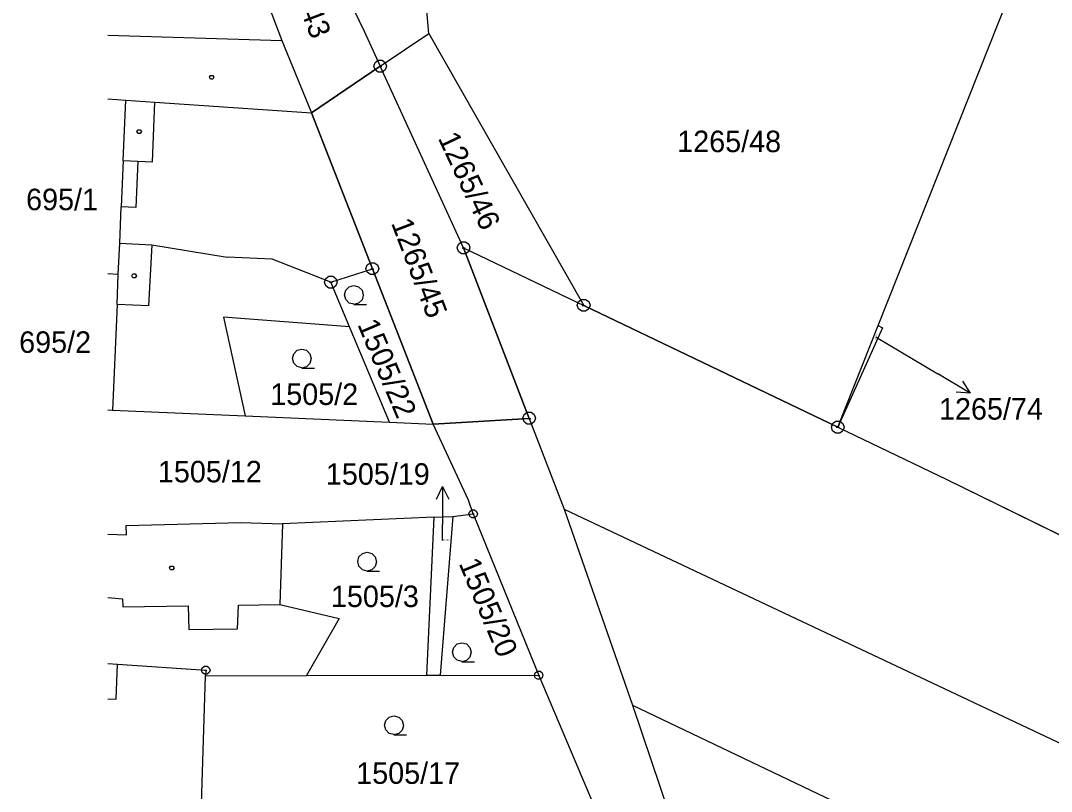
# Model space of a CAD drawing. Extents: x -777309 to -774195, y -1144706 to -1143600.
# Drawn here: x -777306.9 to -777225.3, y -1143975 to -1143914.1 of the extents above; entities that cross this region are included whole.
import ezdxf

# ---------------------------------------------------------------- set-up
doc = ezdxf.new("R2010")
doc.units = 0
for name, color, linetype in [('1', 7, 'Continuous'), ('11', 7, 'Continuous'), ('12', 7, 'Continuous'), ('2', 7, 'Continuous'), ('3', 7, 'Continuous'), ('4', 7, 'Continuous'), ('5', 7, 'Continuous'), ('7', 7, 'Continuous'), ('8', 7, 'Continuous')]:
    doc.layers.add(name, color=color, linetype=linetype)

msp = doc.modelspace()

# ---------------------------------------------------------------- linework, layer by layer
at = {"layer": '1'}
for p, q in [((-777286.27, -1143901.3), (-777279.72, -1143914.89)), ((-777239.05, -1143938.18), (-777226.25, -1143905.92)), ((-777288.2, -1143910.44), (-777286.22, -1143915.64)), ((-777274.6, -1143915.07), (-777274.79, -1143912.96)), ((-777279.72, -1143914.89), (-777278.44, -1143917.67)), ((-777286.22, -1143915.64), (-777283.88, -1143921.35)), ((-777278.44, -1143917.67), (-777274.6, -1143915.07)), ((-777283.88, -1143921.35), (-777278.44, -1143917.67)), ((-777271.84, -1143932.03), (-777278.44, -1143917.67)), ((-777300, -1143920.249), (-777298.57, -1143920.35)), ((-777298.57, -1143920.35), (-777296.28, -1143920.51)), ((-777296.28, -1143920.51), (-777283.88, -1143921.35)), ((-777279.06, -1143933.68), (-777283.88, -1143921.35)), ((-777299.16, -1143934.11), (-777299.05, -1143931.67)), ((-777299.05, -1143931.67), (-777296.52, -1143931.78)), ((-777296.52, -1143931.78), (-777290.55, -1143932.77)), ((-777287, -1143932.91), (-777290.55, -1143932.77)), ((-777271.84, -1143932.03), (-777266.65, -1143945.51)), ((-777271.84, -1143932.03), (-777262.34, -1143936.58)), ((-777282.34, -1143934.75), (-777287, -1143932.91)), ((-777300, -1143934.058), (-777299.16, -1143934.11)), ((-777282.34, -1143934.75), (-777279.06, -1143933.68)), ((-777277.16, -1143938.54), (-777279.06, -1143933.68)), ((-777280.87, -1143938.26), (-777282.34, -1143934.75)), ((-777242.24, -1143946.21), (-777262.34, -1143936.58)), ((-777280.87, -1143938.26), (-777290.83, -1143937.5)), ((-777290.83, -1143937.5), (-777289.12, -1143945.32)), ((-777277.71, -1143945.82), (-777280.87, -1143938.26)), ((-777274.26, -1143945.97), (-777277.16, -1143938.54)), ((-777242.24, -1143946.21), (-777239.05, -1143938.18)), ((-777238.7, -1143938.36), (-777242.24, -1143946.21)), ((-777239.05, -1143938.18), (-777238.7, -1143938.36)), ((-777300, -1143944.843), (-777299.61, -1143944.86)), ((-777299.61, -1143944.86), (-777289.12, -1143945.32)), ((-777289.12, -1143945.32), (-777277.71, -1143945.82)), ((-777277.71, -1143945.82), (-777274.26, -1143945.97)), ((-777266.65, -1143945.51), (-777274.26, -1143945.97)), ((-777266.65, -1143945.51), (-777263.88, -1143952.69)), ((-777271.45, -1143951.98), (-777274.26, -1143945.97)), ((-777242.24, -1143946.21), (-777233.61, -1143950.34)), ((-777233.61, -1143950.34), (-777182.11, -1143975.59)), ((-777271.08, -1143953.07), (-777271.45, -1143951.98)), ((-777272.69, -1143953.26), (-777271.08, -1143953.07)), ((-777271.08, -1143953.07), (-777265.9, -1143965.83)), ((-777263.88, -1143952.69), (-777214.44, -1143976.01)), ((-777263.88, -1143952.69), (-777258.48, -1143968.19)), ((-777298.53, -1143953.99), (-777289.46, -1143953.75)), ((-777298.52, -1143954.72), (-777298.53, -1143953.99)), ((-777289.46, -1143953.75), (-777286.17, -1143953.86)), ((-777286.17, -1143953.86), (-777286.39, -1143960.23)), ((-777274.18, -1143953.33), (-777286.17, -1143953.86)), ((-777274.76, -1143965.81), (-777274.18, -1143953.33)), ((-777274.18, -1143953.33), (-777272.69, -1143953.26)), ((-777272.69, -1143953.26), (-777273.69, -1143965.81)), ((-777300, -1143954.654), (-777298.52, -1143954.72)), ((-777286.39, -1143960.23), (-777281.7, -1143961.34)), ((-777281.7, -1143961.34), (-777284.26, -1143965.84)), ((-777300, -1143964.887), (-777299.23, -1143964.94)), ((-777299.23, -1143964.94), (-777292.24, -1143965.43)), ((-777292.24, -1143965.43), (-777292.26, -1143965.88)), ((-777292.6, -1143976.92), (-777292.26, -1143965.88)), ((-777292.26, -1143965.88), (-777284.26, -1143965.84)), ((-777284.26, -1143965.84), (-777274.76, -1143965.81)), ((-777274.76, -1143965.81), (-777273.69, -1143965.81)), ((-777273.69, -1143965.81), (-777265.9, -1143965.83)), ((-777265.9, -1143965.83), (-777261.12, -1143977.11)), ((-777258.48, -1143968.19), (-777252.93, -1143984.66)), ((-777258.48, -1143968.19), (-777214.18, -1143989.29))]:
    msp.add_line(p, q, dxfattribs=at)
msp.add_lwpolyline([(-777274.6, -1143915.07), (-777269.54, -1143923.97), (-777262.34, -1143936.58)], dxfattribs=at)
at = {"layer": '11'}
msp.add_lwpolyline([(-777286.27, -1143901.3), (-777279.72, -1143914.89), (-777278.44, -1143917.67), (-777283.88, -1143921.35), (-777279.06, -1143933.68), (-777277.16, -1143938.54), (-777274.26, -1143945.97), (-777266.65, -1143945.51), (-777271.84, -1143932.03), (-777262.34, -1143936.58), (-777242.24, -1143946.21), (-777233.61, -1143950.34), (-777182.11, -1143975.59)], dxfattribs=at)
at = {"layer": '12'}
for p, q in [((-777300, -1143920.249), (-777298.57, -1143920.35)), ((-777298.77, -1143925.12), (-777298.57, -1143920.35)), ((-777298.77, -1143925.12), (-777298.93, -1143928.78)), ((-777299.05, -1143931.67), (-777298.93, -1143928.78)), ((-777299.16, -1143934.11), (-777299.05, -1143931.67)), ((-777300, -1143934.058), (-777299.16, -1143934.11)), ((-777300, -1143934.058), (-777299.16, -1143934.11)), ((-777299.26, -1143936.5), (-777299.16, -1143934.11)), ((-777299.26, -1143936.5), (-777299.61, -1143944.86)), ((-777300, -1143944.843), (-777299.61, -1143944.86))]:
    msp.add_line(p, q, dxfattribs=at)
at = {"layer": '3'}
for points in [[(-777280.51, -1143936.49), (-777280.89, -1143936.39), (-777281.16, -1143936.12), (-777281.26, -1143935.75), (-777281.16, -1143935.38), (-777280.89, -1143935.11), (-777280.52, -1143935.01), (-777280.15, -1143935.11), (-777279.88, -1143935.38), (-777279.78, -1143935.76), (-777279.88, -1143936.14), (-777280.15, -1143936.41), (-777280.53, -1143936.51), (-777279.53, -1143936.51)], [(-777284.63, -1143941.51), (-777285.01, -1143941.41), (-777285.28, -1143941.14), (-777285.38, -1143940.77), (-777285.28, -1143940.4), (-777285.01, -1143940.13), (-777284.64, -1143940.03), (-777284.27, -1143940.13), (-777284, -1143940.4), (-777283.9, -1143940.78), (-777284, -1143941.16), (-777284.27, -1143941.43), (-777284.65, -1143941.53), (-777283.65, -1143941.53)], [(-777279.47, -1143957.58), (-777279.85, -1143957.48), (-777280.12, -1143957.21), (-777280.22, -1143956.84), (-777280.12, -1143956.47), (-777279.85, -1143956.2), (-777279.48, -1143956.1), (-777279.11, -1143956.2), (-777278.84, -1143956.47), (-777278.74, -1143956.85), (-777278.84, -1143957.23), (-777279.11, -1143957.5), (-777279.49, -1143957.6), (-777278.49, -1143957.6)], [(-777271.97, -1143964.73), (-777272.35, -1143964.63), (-777272.62, -1143964.36), (-777272.72, -1143963.99), (-777272.62, -1143963.62), (-777272.35, -1143963.35), (-777271.98, -1143963.25), (-777271.61, -1143963.35), (-777271.34, -1143963.62), (-777271.24, -1143964), (-777271.34, -1143964.38), (-777271.61, -1143964.65), (-777271.99, -1143964.75), (-777270.99, -1143964.75)], [(-777277.34, -1143970.52), (-777277.72, -1143970.42), (-777277.99, -1143970.15), (-777278.09, -1143969.78), (-777277.99, -1143969.41), (-777277.72, -1143969.14), (-777277.35, -1143969.04), (-777276.98, -1143969.14), (-777276.71, -1143969.41), (-777276.61, -1143969.79), (-777276.71, -1143970.17), (-777276.98, -1143970.44), (-777277.36, -1143970.54), (-777276.36, -1143970.54)]]:
    msp.add_lwpolyline(points, dxfattribs=at)
at = {"layer": '4'}
for p, q in [((-777300, -1143915.214), (-777286.22, -1143915.64)), ((-777298.77, -1143925.12), (-777298.57, -1143920.35)), ((-777296.46, -1143925.22), (-777296.28, -1143920.51)), ((-777298.77, -1143925.12), (-777298.93, -1143928.78)), ((-777298.77, -1143925.12), (-777297.62, -1143925.17)), ((-777297.62, -1143925.17), (-777297.77, -1143928.83)), ((-777297.62, -1143925.17), (-777296.46, -1143925.22)), ((-777299.05, -1143931.67), (-777298.93, -1143928.78)), ((-777297.77, -1143928.83), (-777298.93, -1143928.78)), ((-777296.52, -1143931.78), (-777296.78, -1143936.6)), ((-777299.26, -1143936.5), (-777299.16, -1143934.11)), ((-777299.26, -1143936.5), (-777299.61, -1143944.86)), ((-777296.78, -1143936.6), (-777299.26, -1143936.5)), ((-777300, -1143959.686), (-777298.83, -1143959.77)), ((-777298.83, -1143959.77), (-777298.81, -1143960.42)), ((-777298.81, -1143960.42), (-777293.64, -1143960.34)), ((-777293.64, -1143960.34), (-777293.58, -1143962.2)), ((-777289.73, -1143962.14), (-777289.65, -1143960.28)), ((-777289.65, -1143960.28), (-777286.39, -1143960.23)), ((-777293.58, -1143962.2), (-777289.73, -1143962.14)), ((-777299.34, -1143967.71), (-777299.23, -1143964.94)), ((-777300, -1143967.682), (-777299.34, -1143967.71))]:
    msp.add_line(p, q, dxfattribs=at)
at = {"layer": '5'}
for points in [[(-777291.68, -1143918.39), (-777291.59, -1143918.54), (-777291.68, -1143918.69), (-777291.86, -1143918.69), (-777291.95, -1143918.54), (-777291.86, -1143918.39)], [(-777297.42, -1143922.69), (-777297.33, -1143922.84), (-777297.42, -1143922.99), (-777297.6, -1143922.99), (-777297.69, -1143922.84), (-777297.6, -1143922.69)], [(-777297.82, -1143934.09), (-777297.73, -1143934.24), (-777297.82, -1143934.39), (-777298, -1143934.39), (-777298.09, -1143934.24), (-777298, -1143934.09)], [(-777294.84, -1143957.19), (-777294.75, -1143957.34), (-777294.84, -1143957.49), (-777295.02, -1143957.49), (-777295.11, -1143957.34), (-777295.02, -1143957.19)]]:
    msp.add_lwpolyline(points, close=True, dxfattribs=at)
at = {"layer": '7'}
for p, q in [((-777239.2, -1143939.1), (-777234.34, -1143941.99)), ((-777231.761, -1143943.523), (-777234.34, -1143941.99)), ((-777273.5, -1143950.91), (-777273.5, -1143953.91)), ((-777273.5, -1143955.17), (-777273.5, -1143953.91))]:
    msp.add_line(p, q, dxfattribs=at)
for points in [[(-777232.365, -1143942.582), (-777231.761, -1143943.523), (-777232.876, -1143943.442)], [(-777274, -1143951.91), (-777273.5, -1143950.91), (-777273, -1143951.91)]]:
    msp.add_lwpolyline(points, dxfattribs=at)
at = {"layer": '8'}
for p, q in [((-777278.56, -1143917.67), (-777278.32, -1143917.67)), ((-777271.96, -1143932.03), (-777271.72, -1143932.03)), ((-777279.18, -1143933.68), (-777278.94, -1143933.68)), ((-777282.46, -1143934.75), (-777282.22, -1143934.75)), ((-777262.46, -1143936.58), (-777262.22, -1143936.58)), ((-777266.77, -1143945.51), (-777266.53, -1143945.51)), ((-777242.36, -1143946.21), (-777242.12, -1143946.21)), ((-777271.16, -1143953.07), (-777271, -1143953.07)), ((-777292.32, -1143965.43), (-777292.16, -1143965.43)), ((-777265.98, -1143965.83), (-777265.82, -1143965.83))]:
    msp.add_line(p, q, dxfattribs=at)
for points in [[(-777278.29, -1143917.19), (-777278.04, -1143917.37), (-777277.94, -1143917.66), (-777278.04, -1143917.95), (-777278.29, -1143918.13), (-777278.6, -1143918.13), (-777278.85, -1143917.95), (-777278.95, -1143917.66), (-777278.85, -1143917.37), (-777278.6, -1143917.19)], [(-777271.69, -1143931.55), (-777271.44, -1143931.73), (-777271.34, -1143932.02), (-777271.44, -1143932.31), (-777271.69, -1143932.49), (-777272, -1143932.49), (-777272.25, -1143932.31), (-777272.35, -1143932.02), (-777272.25, -1143931.73), (-777272, -1143931.55)], [(-777278.91, -1143933.2), (-777278.66, -1143933.38), (-777278.56, -1143933.67), (-777278.66, -1143933.96), (-777278.91, -1143934.14), (-777279.22, -1143934.14), (-777279.47, -1143933.96), (-777279.57, -1143933.67), (-777279.47, -1143933.38), (-777279.22, -1143933.2)], [(-777282.19, -1143934.27), (-777281.94, -1143934.45), (-777281.84, -1143934.74), (-777281.94, -1143935.03), (-777282.19, -1143935.21), (-777282.5, -1143935.21), (-777282.75, -1143935.03), (-777282.85, -1143934.74), (-777282.75, -1143934.45), (-777282.5, -1143934.27)], [(-777262.19, -1143936.1), (-777261.94, -1143936.28), (-777261.84, -1143936.57), (-777261.94, -1143936.86), (-777262.19, -1143937.04), (-777262.5, -1143937.04), (-777262.75, -1143936.86), (-777262.85, -1143936.57), (-777262.75, -1143936.28), (-777262.5, -1143936.1)], [(-777266.5, -1143945.03), (-777266.25, -1143945.21), (-777266.15, -1143945.5), (-777266.25, -1143945.79), (-777266.5, -1143945.97), (-777266.81, -1143945.97), (-777267.06, -1143945.79), (-777267.16, -1143945.5), (-777267.06, -1143945.21), (-777266.81, -1143945.03)], [(-777242.09, -1143945.73), (-777241.84, -1143945.91), (-777241.74, -1143946.2), (-777241.84, -1143946.49), (-777242.09, -1143946.67), (-777242.4, -1143946.67), (-777242.65, -1143946.49), (-777242.75, -1143946.2), (-777242.65, -1143945.91), (-777242.4, -1143945.73)], [(-777270.979, -1143952.748), (-777270.812, -1143952.869), (-777270.745, -1143953.063), (-777270.812, -1143953.258), (-777270.979, -1143953.378), (-777271.187, -1143953.378), (-777271.355, -1143953.258), (-777271.422, -1143953.063), (-777271.355, -1143952.869), (-777271.187, -1143952.748)], [(-777292.14, -1143965.108), (-777291.972, -1143965.229), (-777291.905, -1143965.423), (-777291.972, -1143965.618), (-777292.14, -1143965.738), (-777292.347, -1143965.738), (-777292.515, -1143965.618), (-777292.582, -1143965.423), (-777292.515, -1143965.229), (-777292.347, -1143965.108)], [(-777265.799, -1143965.508), (-777265.632, -1143965.629), (-777265.565, -1143965.823), (-777265.632, -1143966.018), (-777265.799, -1143966.138), (-777266.007, -1143966.138), (-777266.175, -1143966.018), (-777266.242, -1143965.823), (-777266.175, -1143965.629), (-777266.007, -1143965.508)]]:
    msp.add_lwpolyline(points, close=True, dxfattribs=at)

# ---------------------------------------------------------------- texts
at = {"layer": '2'}
for s, height, rotation, p in [('1265/43', 1.7, 290.66149, (-777286.771, -1143907.927)), ('1265/46', 1.7, 295.18786, (-777273.903, -1143923.345)), ('1265/45', 1.7, 290.94797, (-777277.6, -1143930.057)), ('1505/22', 1.7, 292.83873, (-777280.268, -1143938.072)), ('1265/74', 0.1, 72.88023, (-777239.249, -1143939.355)), ('1505/20', 1.7, 292.72414, (-777272.248, -1143956.972))]:
    msp.add_text(s, height=height, rotation=rotation, dxfattribs=at).set_placement(p)
for s, height, p in [('1265/48', 1.7, (-777254.944, -1143924.46)), ('695/1', 1.7, (-777306.453, -1143929.05)), ('695/2', 1.7, (-777307.003, -1143940.33)), ('1505/2', 1.7, (-777287.137, -1143944.45)), ('1505/12', 1.7, (-777296.027, -1143950.57)), ('1505/19', 0.1, (-777273.477, -1143955.17)), ('1505/3', 1.7, (-777282.337, -1143960.43)), ('1505/17', 1.7, (-777280.337, -1143974.41))]:
    msp.add_text(s, height=height, dxfattribs=at).set_placement(p)
at = {"layer": '7'}
for s, p in [('1265/74', (-777234.234, -1143945.61)), ('1505/19', (-777282.74, -1143950.76))]:
    msp.add_text(s, height=1.7, dxfattribs=at).set_placement(p)

doc.saveas('drawing.dxf')
